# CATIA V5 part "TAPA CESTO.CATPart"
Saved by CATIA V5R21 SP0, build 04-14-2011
Part number: TAPA CESTO
Bounding box of the stored display mesh (mm): x -190 to 190, y -190 to 190, z 0 to 3
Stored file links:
  D:\MENA 3D\BISMARK\TAPA CESTO.CATPart
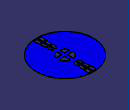
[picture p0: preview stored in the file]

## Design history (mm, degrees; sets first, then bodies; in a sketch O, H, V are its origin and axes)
Body1 (main body)
  Set1
    Sketch1 on xy-plane, origin (0, 0, 0), H (1, 0, 0), V (0, 1, 0)
      circle A1 centre (0, 0) radius 190
      radius A1 = 190
  Pad1: profile Sketch1, direction (0, 0, 1), length 3
  Sketch2 on end face of Pad1, origin (0, 0, 3), H (1, 0, 0), V (0, 1, 0)
    arc A1 centre (0, 0) radius 70 from (14.4079, 68.5012) to (4.5, 69.8552) ccw
    arc A2 centre (0, 0) radius 47.5 from (-9.5, 46.5403) to (-47.1482, 5.7707) ccw
    line L1 (9.5, 46.5403) -> (9.5, 5.7707)
    point P2 (9.5, -46.5403)
    line L2 (-9.5, 46.5403) -> (-9.5, 5.7707)
    point P4 (-9.5, -46.5403)
    line L3 (-47.1482, 5.7707) -> (-9.5, 5.7707)
    point P6 (47.1482, 5.7707)
    point P7 (-45.6206, -13.2293)
    line L4 (-45.6206, -13.2293) -> (-9.5, -13.2293)
    line L5 (9.5, 5.7707) -> (47.1482, 5.7707)
    arc A3 centre (0, 0) radius 47.5 from (47.1482, 5.7707) to (9.5, 46.5403) ccw
    line L6 (9.5, -13.2293) -> (9.5, -46.5403)
    point P11 (9.5, -13.2293)
    line L7 (-9.5, -13.2293) -> (-9.5, -46.5403)
    arc A4 centre (0, 0) radius 47.5 from (-45.6206, -13.2293) to (-9.5, -46.5403) ccw
    arc A5 centre (0, 0) radius 47.5 from (9.5, -46.5403) to (45.6206, -13.2293) ccw
    line L8 (9.5, -13.2293) -> (45.6206, -13.2293)
    point P13 (0, 118.1695)
    line L9 (4.5, 182.9447) -> (4.5, 149.1507)
    arc A6 centre (0, 0) radius 183 from (26.4211, 181.0827) to (4.5, 182.9447) ccw
    reference projected circle E1 centre (0, 0) radius 190 from edge [face of Pad1 from Sketch1.A1 | end face of Pad1]
    point P14 (4.5, 182.9447)
    point P15 (4.5, 69.8552)
    arc A7 centre (0, 0) radius 109.1561 from (17.434, 107.7548) to (4.5, 109.0633) ccw
    arc A8 centre (0, 0) radius 149.2186 from (22.4263, 147.5237) to (4.5, 149.1507) ccw
    line L10 (17.434, 107.7548) -> (24.3974, 141.0649)
    line L11 (22.4263, 147.5237) -> (26.4211, 181.0827)
    point P16 (26.4211, 181.0827)
    line L12 (14.4079, 68.5012) -> (23.3183, 98.5274)
    point P17 (14.4079, 68.5012)
    point P18 (17.434, 107.7548)
    point P19 (22.4263, 147.5237)
    arc A9 centre (0, 0) radius 101.2492 from (23.3183, 98.5274) to (4.5, 101.1491) ccw
    arc A10 centre (0, 0) radius 143.1591 from (24.3974, 141.0649) to (4.5, 143.0884) ccw
    point P20 (23.3183, 98.5274)
    point P21 (24.3974, 141.0649)
    point P22 (4.5, 149.1507)
    point P23 (4.5, 143.0884)
    point P24 (4.5, 109.0633)
    point P25 (4.5, 101.1491)
    line L13 (4.5, 101.1491) -> (4.5, 69.8552)
    line L14 (4.5, 143.0884) -> (4.5, 109.0633)
    point P26 (0, 118.1695)
    point P27 (-4.5, 182.9447)
    point P28 (-4.5, 69.8552)
    point P29 (-26.4211, 181.0827)
    point P30 (-14.4079, 68.5012)
    point P31 (-17.434, 107.7548)
    point P32 (-22.4263, 147.5237)
    point P33 (-23.3183, 98.5274)
    point P34 (-24.3974, 141.0649)
    point P35 (-4.5, 149.1507)
    point P36 (-4.5, 143.0884)
    point P37 (-4.5, 109.0633)
    point P38 (-4.5, 101.1491)
    arc A11 centre (0, 0) radius 70 from (-14.4079, 68.5012) to (-4.5, 69.8552) cw
    line L15 (-4.5, 182.9447) -> (-4.5, 149.1507)
    arc A12 centre (0, 0) radius 183 from (-26.4211, 181.0827) to (-4.5, 182.9447) cw
    arc A13 centre (0, 0) radius 109.1561 from (-17.434, 107.7548) to (-4.5, 109.0633) cw
    arc A14 centre (0, 0) radius 149.2186 from (-22.4263, 147.5237) to (-4.5, 149.1507) cw
    line L16 (-17.434, 107.7548) -> (-24.3974, 141.0649)
    line L17 (-22.4263, 147.5237) -> (-26.4211, 181.0827)
    line L18 (-14.4079, 68.5012) -> (-23.3183, 98.5274)
    arc A15 centre (0, 0) radius 101.2492 from (-23.3183, 98.5274) to (-4.5, 101.1491) cw
    arc A16 centre (0, 0) radius 143.1591 from (-24.3974, 141.0649) to (-4.5, 143.0884) cw
    line L19 (-4.5, 101.1491) -> (-4.5, 69.8552)
    line L20 (-4.5, 143.0884) -> (-4.5, 109.0633)
    point P40 (0, -118.1695)
    point P41 (4.5, -182.9447)
    point P42 (4.5, -69.8552)
    point P43 (26.4211, -181.0827)
    point P44 (14.4079, -68.5012)
    point P45 (17.434, -107.7548)
    point P46 (22.4263, -147.5237)
    point P47 (23.3183, -98.5274)
    point P48 (24.3974, -141.0649)
    point P49 (4.5, -149.1507)
    point P50 (4.5, -143.0884)
    point P51 (4.5, -109.0633)
    point P52 (4.5, -101.1491)
    point P53 (0, -118.1695)
    point P54 (-4.5, -182.9447)
    point P55 (-4.5, -69.8552)
    point P56 (-26.4211, -181.0827)
    point P57 (-14.4079, -68.5012)
    point P58 (-17.434, -107.7548)
    point P59 (-22.4263, -147.5237)
    point P60 (-23.3183, -98.5274)
    point P61 (-24.3974, -141.0649)
    point P62 (-4.5, -149.1507)
    point P63 (-4.5, -143.0884)
    point P64 (-4.5, -109.0633)
    point P65 (-4.5, -101.1491)
    arc A17 centre (0, 0) radius 70 from (14.4079, -68.5012) to (4.5, -69.8552) cw
    line L21 (4.5, -182.9447) -> (4.5, -149.1507)
    arc A18 centre (0, 0) radius 183 from (26.4211, -181.0827) to (4.5, -182.9447) cw
    arc A19 centre (0, 0) radius 109.1561 from (17.434, -107.7548) to (4.5, -109.0633) cw
    arc A20 centre (0, 0) radius 149.2186 from (22.4263, -147.5237) to (4.5, -149.1507) cw
    line L22 (17.434, -107.7548) -> (24.3974, -141.0649)
    line L23 (22.4263, -147.5237) -> (26.4211, -181.0827)
    line L24 (14.4079, -68.5012) -> (23.3183, -98.5274)
    arc A21 centre (0, 0) radius 101.2492 from (23.3183, -98.5274) to (4.5, -101.1491) cw
    arc A22 centre (0, 0) radius 143.1591 from (24.3974, -141.0649) to (4.5, -143.0884) cw
    line L25 (4.5, -101.1491) -> (4.5, -69.8552)
    line L26 (4.5, -143.0884) -> (4.5, -109.0633)
    arc A23 centre (0, 0) radius 70 from (-14.4079, -68.5012) to (-4.5, -69.8552) ccw
    line L27 (-4.5, -182.9447) -> (-4.5, -149.1507)
    arc A24 centre (0, 0) radius 183 from (-26.4211, -181.0827) to (-4.5, -182.9447) ccw
    arc A25 centre (0, 0) radius 109.1561 from (-17.434, -107.7548) to (-4.5, -109.0633) ccw
    arc A26 centre (0, 0) radius 149.2186 from (-22.4263, -147.5237) to (-4.5, -149.1507) ccw
    line L28 (-17.434, -107.7548) -> (-24.3974, -141.0649)
    line L29 (-22.4263, -147.5237) -> (-26.4211, -181.0827)
    line L30 (-14.4079, -68.5012) -> (-23.3183, -98.5274)
    arc A27 centre (0, 0) radius 101.2492 from (-23.3183, -98.5274) to (-4.5, -101.1491) ccw
    arc A28 centre (0, 0) radius 143.1591 from (-24.3974, -141.0649) to (-4.5, -143.0884) ccw
    line L31 (-4.5, -101.1491) -> (-4.5, -69.8552)
    line L32 (-4.5, -143.0884) -> (-4.5, -109.0633)
    radius A1 = 70
    radius A2 = 47.5
    distance L2 L1 = 19
    distance L3 L4 = 19
    distance A6 E1 = 7
    distance P17 P15 = 10
    distance P25 P20 = 19
    distance P24 P18 = 13
    distance P23 P21 = 20
    distance P22 P19 = 18
    distance P14 P16 = 22
    coincidence: P2 A2, P4 A2, P6 A2, P7 A2, L3 L5, A2 A3, L4 P11, L1 L6, L2 L7, A2 A4, A4 A5, L4 L8, P13 V, L9 P23, L9 P25, L9 L13, L9 L14
    vertical: L1 V, L2 V, L6 V, L7 V, L9 V, L13 V, L14 V
    symmetry: L2 L1 V, P13 P26 V, P14 P27 V, P15 P28 V, P16 P29 V, P17 P30 V, P18 P31 V, P19 P32 V, P20 P33 V, P21 P34 V, P22 P35 V, P23 P36 V, P24 P37 V, P25 P38 V, A1 A11 V, L9 L15 V, A6 A12 V, A7 A13 V, A8 A14 V, L10 L16 V, L11 L17 V, L12 L18 V, A9 A15 V, A10 A16 V, L13 L19 V, L14 L20 V, P13 P40 H, P14 P41 H, P15 P42 H, P16 P43 H, P17 P44 H, P18 P45 H, P19 P46 H, P20 P47 H, P21 P48 H, P22 P49 H, P23 P50 H, P24 P51 H, P25 P52 H, P26 P53 H, P27 P54 H, P28 P55 H, P29 P56 H, P30 P57 H, P31 P58 H, P32 P59 H, P33 P60 H, P34 P61 H, P35 P62 H, P36 P63 H, P37 P64 H, P38 P65 H, A1 A17 H, L9 L21 H, A6 A18 H, A7 A19 H, A8 A20 H, L10 L22 H, L11 L23 H, L12 L24 H, A9 A21 H, A10 A22 H, L13 L25 H, L14 L26 H, A11 A23 H, L15 L27 H, A12 A24 H, A13 A25 H, A14 A26 H, L16 L28 H, L17 L29 H, L18 L30 H, A15 A27 H, A16 A28 H, L19 L31 H, L20 L32 H
    horizontal: L3 H, L4 H, L5 H, L8 H
  Pocket1: profile Sketch2, direction (0, 0, -1), through (limit type 6)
